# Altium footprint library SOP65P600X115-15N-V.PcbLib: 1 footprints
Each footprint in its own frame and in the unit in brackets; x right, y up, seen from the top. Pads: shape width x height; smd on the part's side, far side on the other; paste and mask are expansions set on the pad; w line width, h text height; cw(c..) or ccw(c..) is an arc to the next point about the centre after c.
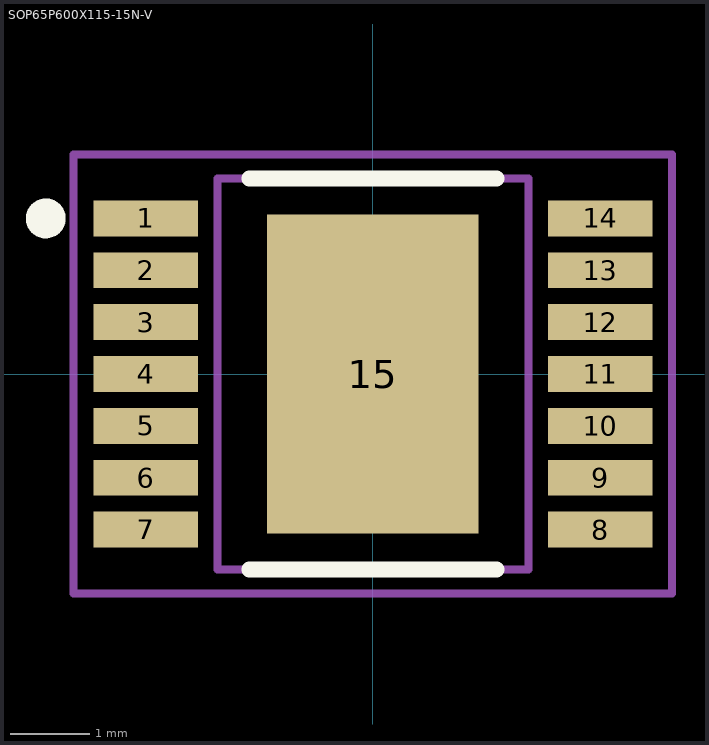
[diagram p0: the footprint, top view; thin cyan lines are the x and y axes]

## SOP65P600X115-15N-V [mm] "SOP,0.65mm pitch;14 pin,3.90mm W X 4.90mm L X 1.15mm H body (w/thermal tab)"
height 1.15
pads (15):
  rect 1.31x0.45 smd paste+0 mask+0: 1(-2.85,1.95) 2(-2.85,1.3) 3(-2.85,0.65) 4(-2.85,0) 5(-2.85,-0.65) 6(-2.85,-1.3) 7(-2.85,-1.95) 8(2.85,-1.95) 9(2.85,-1.3) 10(2.85,-0.65) 11(2.85,0) 12(2.85,0.65) 13(2.85,1.3) 14(2.85,1.95)
  rect 2.65x4 smd paste-2.65 mask+0: 15(0,0)
Top Overlay:
  circle w0.25: c-4.1,1.95 r0.125
  lines w0.2: -1.55,-2.45 1.55,-2.45 ; -1.55,2.45 1.55,2.45
Top Paste:
  region: 1.325,2 -1.325,2 -1.325,0.15 1.325,0.15
  region: -1.325,-2 1.325,-2 1.325,-0.15 -1.325,-0.15
M3 (ASY_Text_Top):
  text ".DESIGNATOR" at 0,0 h1.2
M13 (CMP_Body_OTL_Top):
  lines w0.1: -1.95,-2.45 1.95,-2.45 1.95,2.45 -1.95,2.45 -1.95,-2.45
M15 (CMP_Courtyard_Top):
  lines w0.1: -0.5,0 0.5,0 ; 0,-0.5 0,0.5 ; -3.75,-2.75 3.75,-2.75 3.75,2.75 -3.75,2.75 -3.75,-2.75
3D body "PG-TSDSO-14-22.stp": height 1.16, standoff 0, extent -3,-2.45 3,2.45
